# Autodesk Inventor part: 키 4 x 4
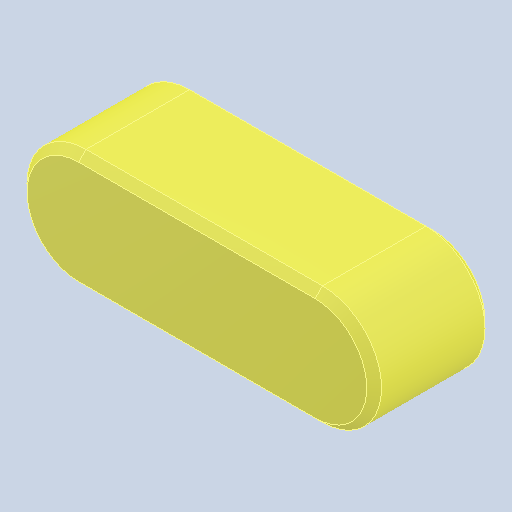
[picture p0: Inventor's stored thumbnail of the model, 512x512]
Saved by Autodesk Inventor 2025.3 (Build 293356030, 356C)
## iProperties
Created: 2025-08
Part Number: 키 4 x 4
Material: 강철, 연강
Description: 키 및 해당 키홈
Document SubType Name: Modeling
Designer: infra011
Density: 7.86 g/cm^3
Appearance: 기본값
Author: jhkim
Sending System: Autodesk Inventor 2026
Preprocessor: ST-DEVELOPER v20.1
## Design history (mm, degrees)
feature "Solid1"
node "솔리드1"
